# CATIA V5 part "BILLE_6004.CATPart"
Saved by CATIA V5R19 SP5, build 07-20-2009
Part number: Michaud_Chailly_L16004_PART3
Bounding box of the stored display mesh (mm): x 4.2 to 10.8, y 11.714 to 18.286, z -3.29 to 3.29
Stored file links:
  O:\4A\TP2 - boitier prelude\BOITIER ARRIERE HONDA PRELUDE\Maquette pour eleves\BILLE_6004.CATPart
  O:\4A\TP2 - boitier prelude\BOITIER ARRIERE HONDA PRELUDE\Maquette DMU Kin\ROULEMENT_6004.CATProduct
  O:\4A\TP2 - boitier prelude\BOITIER ARRIERE HONDA PRELUDE\Maquette DMU Kin\BAGUE_INT_6004.CATPart
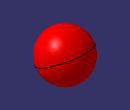
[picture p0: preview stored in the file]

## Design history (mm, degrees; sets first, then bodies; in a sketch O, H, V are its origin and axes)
Set1
  Point1: (0, 0, 0)
  Point2: (1, 0, 0)
  Point3: (0, 1, 0)
  Plane1: type 3Points, Element1 Point1, Element2 Point2, Element3 Point3
Body1 (main body)
  Sketch1 on Plane1, origin (0, 0, 0), H (1, 0, 0), V (0, 1, 0)
    arc A1 centre (7.5, 15) radius 3.3 from (4.2, 15) to (10.8, 15) ccw
    line L1 (4.2, 15) -> (10.8, 15)
    axis line L2 (5.9325, 15) -> (12.5325, 15)
    point P1 (4.2, 15)
    point P2 (10.8, 15)
    point P3 (4.2, 15)
    point P4 (10.8, 15)
    radius A1 = 3.3
    distance L1 H = 15
    distance L2 H = 15
    distance P1 V = 4.2
    coincidence: P1 P3, P2 P4
  Shaft1: profile Sketch1, axis Sketch1.L2, angle 0, second angle 360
